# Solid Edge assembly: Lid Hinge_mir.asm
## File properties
Author: m_hel
Template: Iso Metric Assembly.asm
Last saved by: m_hel
Revision: 4
Application: Solid Edge
Username: m_hel
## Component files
Hinge_mir.psm
Hinge Bolt.par
Lid Hinge.asm
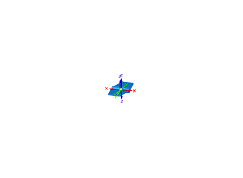
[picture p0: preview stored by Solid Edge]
